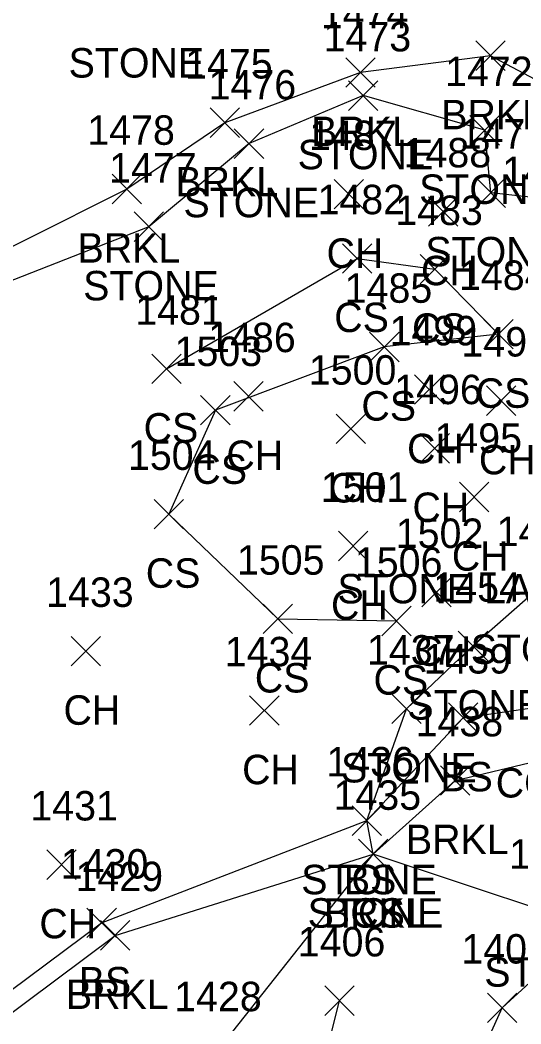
# Model space of a CAD drawing. Extents: x 1599840 to 1601211, y 518904 to 521989.
# Drawn here: x 1600737.9 to 1600771.9, y 521246 to 521314.2 of the extents above; entities that cross this region are included whole.
import ezdxf

# ---------------------------------------------------------------- set-up
doc = ezdxf.new("R2010")
doc.units = 0
for name, color, linetype in [('D_C', 7, 'Continuous'), ('L_A', 7, 'Continuous'), ('L_C', 7, 'Continuous'), ('L_I', 7, 'Continuous'), ('L_TIC', 7, 'Continuous'), ('LASF', 7, 'Continuous'), ('LAWA', 7, 'Continuous'), ('LAWE', 7, 'Continuous'), ('LELB', 7, 'Continuous')]:
    doc.layers.add(name, color=color, linetype=linetype)

msp = doc.modelspace()

# ---------------------------------------------------------------- linework, layer by layer
at = {"layer": 'L_TIC'}
for points in [[(1600768.853, 521310.777), (1600770.853, 521312.777)], [(1600770.853, 521310.777), (1600768.853, 521312.777)], [(1600760.009, 521309.636), (1600762.009, 521311.636)], [(1600762.009, 521309.636), (1600760.009, 521311.636)], [(1600760.198, 521308.066), (1600762.198, 521310.066)], [(1600762.198, 521308.066), (1600760.198, 521310.066)], [(1600750.785, 521306.227), (1600752.785, 521308.227)], [(1600752.785, 521306.227), (1600750.785, 521308.227)], [(1600768.452, 521305.712), (1600770.452, 521307.712)], [(1600770.452, 521305.712), (1600768.452, 521307.712)], [(1600752.437, 521304.807), (1600754.437, 521306.807)], [(1600754.437, 521304.807), (1600752.437, 521306.807)], [(1600744.14, 521301.726), (1600746.14, 521303.726)], [(1600746.14, 521301.726), (1600744.14, 521303.726)], [(1600759.215, 521301.372), (1600761.215, 521303.372)], [(1600761.215, 521301.372), (1600759.215, 521303.372)], [(1600768.876, 521301.473), (1600770.876, 521303.473)], [(1600770.876, 521301.473), (1600768.876, 521303.473)], [(1600765.634, 521300.192), (1600767.634, 521302.192)], [(1600767.634, 521300.192), (1600765.634, 521302.192)], [(1600745.621, 521299.165), (1600747.621, 521301.165)], [(1600747.621, 521299.165), (1600745.621, 521301.165)], [(1600759.786, 521297.014), (1600761.786, 521299.014)], [(1600761.786, 521297.014), (1600759.786, 521299.014)], [(1600765.072, 521296.281), (1600767.072, 521298.281)], [(1600767.072, 521296.281), (1600765.072, 521298.281)], [(1600769.399, 521291.873), (1600771.399, 521293.873)], [(1600771.399, 521291.873), (1600769.399, 521293.873)], [(1600761.632, 521291.002), (1600763.632, 521293.002)], [(1600763.632, 521291.002), (1600761.632, 521293.002)], [(1600746.832, 521289.513), (1600748.832, 521291.513)], [(1600748.832, 521289.513), (1600746.832, 521291.513)], [(1600764.688, 521288.112), (1600766.688, 521290.112)], [(1600766.688, 521288.112), (1600764.688, 521290.112)], [(1600752.409, 521287.651), (1600754.409, 521289.651)], [(1600754.409, 521287.651), (1600752.409, 521289.651)], [(1600769.569, 521287.355), (1600771.569, 521289.355)], [(1600771.569, 521287.355), (1600769.569, 521289.355)], [(1600750.147, 521286.709), (1600752.147, 521288.709)], [(1600752.147, 521286.709), (1600750.147, 521288.709)], [(1600759.359, 521285.444), (1600761.359, 521287.444)], [(1600761.359, 521285.444), (1600759.359, 521287.444)], [(1600765.054, 521284.12), (1600767.054, 521286.12)], [(1600767.054, 521284.12), (1600765.054, 521286.12)], [(1600767.732, 521280.817), (1600769.732, 521282.817)], [(1600769.732, 521280.817), (1600767.732, 521282.817)], [(1600746.979, 521279.655), (1600748.979, 521281.655)], [(1600748.979, 521279.655), (1600746.979, 521281.655)], [(1600759.519, 521277.488), (1600761.519, 521279.488)], [(1600761.519, 521277.488), (1600759.519, 521279.488)], [(1600765.18, 521274.357), (1600767.18, 521276.357)], [(1600767.18, 521274.357), (1600765.18, 521276.357)], [(1600754.387, 521272.546), (1600756.387, 521274.546)], [(1600756.387, 521272.546), (1600754.387, 521274.546)], [(1600762.455, 521272.401), (1600764.455, 521274.401)], [(1600764.455, 521272.401), (1600762.455, 521274.401)], [(1600741.34, 521270.356), (1600743.34, 521272.356)], [(1600743.34, 521270.356), (1600741.34, 521272.356)], [(1600767.657, 521270.705), (1600769.657, 521272.705)], [(1600769.657, 521270.705), (1600767.657, 521272.705)], [(1600753.478, 521266.321), (1600755.478, 521268.321)], [(1600755.478, 521266.321), (1600753.478, 521268.321)], [(1600763.145, 521266.439), (1600765.145, 521268.439)], [(1600765.145, 521266.439), (1600763.145, 521268.439)], [(1600766.997, 521265.834), (1600768.997, 521267.834)], [(1600768.997, 521265.834), (1600766.997, 521267.834)], [(1600766.454, 521261.572), (1600768.454, 521263.572)], [(1600768.454, 521261.572), (1600766.454, 521263.572)], [(1600760.441, 521258.849), (1600762.441, 521260.849)], [(1600762.441, 521258.849), (1600760.441, 521260.849)], [(1600760.441, 521258.849), (1600762.441, 521260.849)], [(1600762.441, 521258.849), (1600760.441, 521260.849)], [(1600760.877, 521256.582), (1600762.877, 521258.582)], [(1600762.877, 521256.582), (1600760.877, 521258.582)], [(1600760.877, 521256.582), (1600762.877, 521258.582)], [(1600762.877, 521256.582), (1600760.877, 521258.582)], [(1600760.877, 521256.582), (1600762.877, 521258.582)], [(1600762.877, 521256.582), (1600760.877, 521258.582)], [(1600739.7, 521255.858), (1600741.7, 521257.858)], [(1600741.7, 521255.858), (1600739.7, 521257.858)], [(1600742.422, 521251.915), (1600744.422, 521253.915)], [(1600744.422, 521251.915), (1600742.422, 521253.915)], [(1600743.345, 521251.061), (1600745.345, 521253.061)], [(1600745.345, 521251.061), (1600743.345, 521253.061)], [(1600758.579, 521246.629), (1600760.579, 521248.629)], [(1600760.579, 521246.629), (1600758.579, 521248.629)], [(1600769.642, 521246.145), (1600771.642, 521248.145)], [(1600771.642, 521246.145), (1600769.642, 521248.145)]]:
    msp.add_lwpolyline(points, dxfattribs=at)
at = {"layer": 'LASF'}
for points in [[(1600787.733, 521301.588), (1600778.08, 521301.561), (1600769.876, 521302.473), (1600769.452, 521306.712), (1600761.198, 521309.066), (1600753.437, 521305.807), (1600746.621, 521300.165), (1600732.332, 521294.559), (1600731.017, 521295.657), (1600727.669, 521298.755)], [(1600773.881, 521253.578), (1600761.877, 521257.582), (1600761.441, 521259.849), (1600764.145, 521267.439), (1600768.657, 521271.705), (1600772.957, 521275.482), (1600776.99, 521277.111), (1600779.773, 521276.79)]]:
    msp.add_lwpolyline(points, dxfattribs=at)
at = {"layer": 'LAWA'}
msp.add_lwpolyline([(1600715.259, 521175.557), (1600743.614, 521209.669), (1600755.161, 521229.873), (1600759.579, 521247.629)], dxfattribs=at)
at = {"layer": 'LAWE'}
for points in [[(1600788.504, 521302.133), (1600779.639, 521306.578), (1600769.853, 521311.777), (1600761.009, 521310.636), (1600751.785, 521307.227), (1600745.14, 521302.726), (1600731.017, 521295.657), (1600729.255, 521276.143), (1600716.099, 521262.819), (1600704.876, 521257.404), (1600692.678, 521234.473)], [(1600710.084, 521218.612), (1600728.191, 521240.002), (1600744.345, 521252.061), (1600761.877, 521257.582), (1600767.454, 521262.572), (1600777.034, 521264.853), (1600779.729, 521268.746)]]:
    msp.add_lwpolyline(points, dxfattribs=at)
at = {"layer": 'LELB'}
for points in [[(1600741.132, 521196.942), (1600761.003, 521225.763), (1600770.642, 521247.145), (1600790.977, 521265.75), (1600800.284, 521274.946), (1600804.556, 521287.901), (1600802.128, 521291.126), (1600804.075, 521295.258), (1600810.479, 521300.323), (1600825.075, 521308.704)], [(1600708.733, 521220.076), (1600727.282, 521240.92), (1600743.422, 521252.915), (1600761.441, 521259.849), (1600767.997, 521266.834), (1600775.487, 521267.923), (1600778.299, 521269.516), (1600777.22, 521270.369), (1600777.984, 521271.944), (1600782.563, 521280.311), (1600784.373, 521283.656), (1600784.535, 521285.275), (1600784.988, 521289.181), (1600784.719, 521292.066), (1600785.198, 521295.053), (1600787.733, 521301.588)], [(1600747.832, 521290.513), (1600760.786, 521298.014), (1600766.072, 521297.281), (1600770.399, 521292.873), (1600762.632, 521292.002), (1600751.147, 521287.709), (1600747.979, 521280.655), (1600755.387, 521273.546), (1600763.455, 521273.401)], [(1600720.395, 521218.327), (1600732.749, 521235.358), (1600751.043, 521243.911), (1600761.877, 521257.582)]]:
    msp.add_lwpolyline(points, dxfattribs=at)

# ---------------------------------------------------------------- texts
at = {"layer": 'D_C'}
msp.add_text('CONCRETE', height=2, dxfattribs=at).set_placement((1600770.204, 521261.418))
at = {"layer": 'L_A'}
for s, p in [('STONE', (1600741.176, 521310.291)), ('BRKL', (1600766.499, 521306.777)), ('BRKL', (1600757.655, 521305.636)), ('STONE', (1600756.741, 521304.066)), ('BRKL', (1600748.43, 521302.227)), ('STONE', (1600764.996, 521301.712)), ('STONE', (1600748.981, 521300.807)), ('BRKL', (1600741.786, 521297.726)), ('STONE', (1600765.419, 521297.473)), ('CH', (1600758.704, 521297.372)), ('CH', (1600765.122, 521296.192)), ('STONE', (1600742.164, 521295.165)), ('CS', (1600759.227, 521293.014)), ('CS', (1600764.513, 521292.281)), ('CS', (1600768.84, 521287.873)), ('CS', (1600761.073, 521287.002)), ('CS', (1600746.273, 521285.513)), ('CH', (1600764.177, 521284.112)), ('CH', (1600751.897, 521283.651)), ('CH', (1600769.057, 521283.355)), ('CS', (1600749.588, 521282.709)), ('CH', (1600758.847, 521281.444)), ('CH', (1600764.542, 521280.12)), ('CH', (1600767.22, 521276.817)), ('CS', (1600746.419, 521275.655)), ('CH', (1600759.007, 521273.488)), ('CH', (1600764.668, 521270.357)), ('STONE', (1600768.5, 521270.482)), ('CS', (1600753.828, 521268.546)), ('CS', (1600761.896, 521268.401)), ('CH', (1600740.828, 521266.356)), ('STONE', (1600764.2, 521266.705)), ('CH', (1600752.966, 521262.321)), ('STONE', (1600759.689, 521262.439)), ('BS', (1600766.438, 521261.834)), ('BRKL', (1600764.1, 521257.572)), ('STONE', (1600756.985, 521254.849)), ('BS', (1600759.882, 521254.849)), ('STONE', (1600757.42, 521252.582)), ('BRKL', (1600758.522, 521252.582)), ('CS', (1600760.318, 521252.582)), ('CH', (1600739.188, 521251.858)), ('STONE', (1600769.424, 521248.578)), ('STONE', (1600769.424, 521248.578)), ('BS', (1600741.863, 521247.915)), ('BRKL', (1600740.991, 521247.061))]:
    msp.add_text(s, height=2, dxfattribs=at).set_placement(p)
at = {"layer": 'L_C'}
msp.add_text('STONE LAID UP ALONG PIPE CUT ON', height=2, dxfattribs=at).set_placement((1600759.447, 521274.594))
at = {"layer": 'L_I'}
for s, p in [('1474', (1600758.317, 521313.636)), ('1473', (1600758.505, 521312.066)), ('1475', (1600749.092, 521310.227)), ('1472', (1600766.76, 521309.712)), ('1476', (1600750.69, 521308.807)), ('1478', (1600742.447, 521305.726)), ('1487', (1600757.523, 521305.372)), ('1471', (1600767.75, 521305.473)), ('1488', (1600763.941, 521304.192)), ('1477', (1600743.928, 521303.165)), ('1489', (1600770.644, 521302.923)), ('1482', (1600758.093, 521301.014)), ('1483', (1600763.379, 521300.281)), ('1484', (1600767.706, 521295.873)), ('1485', (1600759.939, 521295.002)), ('1481', (1600745.706, 521293.513)), ('1499', (1600762.988, 521292.112)), ('1486', (1600750.661, 521291.651)), ('1497', (1600767.876, 521291.355)), ('1503', (1600748.376, 521290.709)), ('1500', (1600757.501, 521289.444)), ('1496', (1600763.306, 521288.12)), ('1495', (1600766.039, 521284.817)), ('1504', (1600745.207, 521283.655)), ('1501', (1600758.314, 521281.488)), ('1455', (1600770.264, 521278.482)), ('1502', (1600763.409, 521278.357)), ('1505', (1600752.616, 521276.546)), ('1506', (1600760.629, 521276.401)), ('1433', (1600739.647, 521274.356)), ('1454', (1600765.964, 521274.705)), ('1434', (1600751.785, 521270.321)), ('1437', (1600761.453, 521270.439)), ('1439', (1600765.297, 521269.834)), ('1438', (1600764.761, 521265.572)), ('1436', (1600758.694, 521262.849)), ('1436', (1600758.694, 521262.849)), ('1435', (1600759.184, 521260.582)), ('1435', (1600759.184, 521260.582)), ('1435', (1600759.184, 521260.582)), ('1431', (1600738.574, 521259.858)), ('1407', (1600771.109, 521256.578)), ('1407', (1600771.109, 521256.578)), ('1430', (1600740.643, 521255.915)), ('1429', (1600741.645, 521255.061)), ('1406', (1600756.752, 521250.629)), ('1405', (1600767.871, 521250.145)), ('1428', (1600748.35, 521246.911))]:
    msp.add_text(s, height=2, dxfattribs=at).set_placement(p)

doc.saveas('drawing.dxf')
